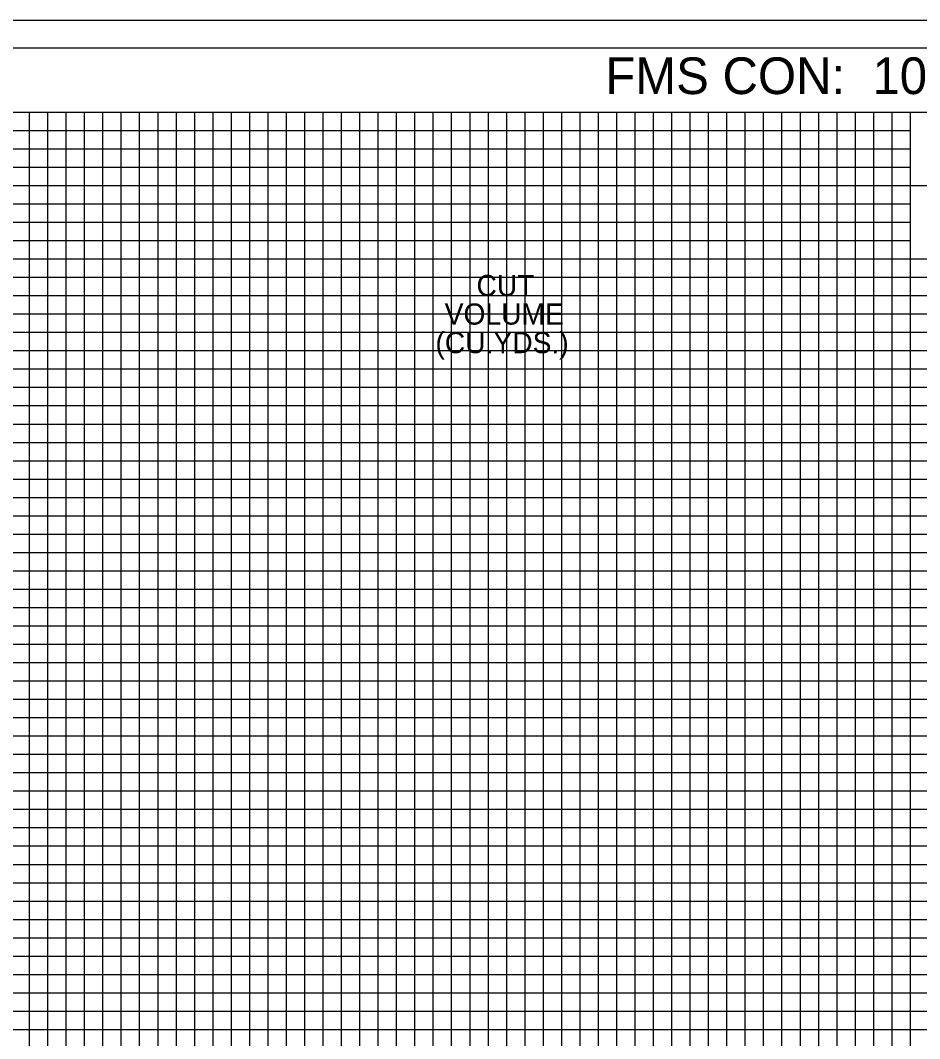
# Model space of a CAD drawing. Extents: x -10 to 342, y -5 to 215.
# Drawn here: x 258.5 to 307.5, y 159.5 to 215 of the extents above; entities that cross this region are included whole.
import ezdxf

# ---------------------------------------------------------------- set-up
doc = ezdxf.new("R2010")
doc.units = 0
for name, color, linetype in [('SHEET_BORDER', 7, 'Continuous'), ('SHEET_BORDER_TX', 7, 'Continuous'), ('SHEET_PLOTTING_SHAPE', 7, 'Continuous'), ('SHEET_PROJ_NUMBER', 7, 'Continuous'), ('XS_SHEET_EW_TX_VOLUME', 7, 'Continuous'), ('XS_SHEET_MAJOR_GRIDS', 7, 'Continuous'), ('XS_SHEET_MEDIUM_GRIDS', 7, 'Continuous'), ('XS_SHEET_MINOR_GRIDS', 7, 'Continuous')]:
    doc.layers.add(name, color=color, linetype=linetype)

msp = doc.modelspace()

# ---------------------------------------------------------------- linework, layer by layer
at = {"layer": 'SHEET_BORDER'}
for p, q in [((-9.8, 213.5), (342.2, 213.5)), ((5, 210), (340, 210)), ((307, 206), (340, 206))]:
    msp.add_line(p, q, dxfattribs=at)
at = {"layer": 'SHEET_PLOTTING_SHAPE'}
msp.add_lwpolyline([(-3.8, -5), (342.2, -5), (342.2, 215), (-3.8, 215)], close=True, dxfattribs=at)
at = {"layer": 'SHEET_PROJ_NUMBER'}
for q in [(307, 210), (340, 202)]:
    msp.add_line((307, 202), q, dxfattribs=at)
at = {"layer": 'XS_SHEET_MAJOR_GRIDS'}
for p, q in [((260, 0), (260, 210)), ((270, 0), (270, 210)), ((280, 0), (280, 210)), ((290, 0), (290, 210)), ((300, 0), (300, 210)), ((5, 200), (340, 200)), ((5, 190), (340, 190)), ((5, 180), (340, 180)), ((5, 170), (340, 170)), ((5, 160), (340, 160))]:
    msp.add_line(p, q, dxfattribs=at)
at = {"layer": 'XS_SHEET_MEDIUM_GRIDS'}
for p, q in [((265, 0), (265, 210)), ((275, 0), (275, 210)), ((285, 0), (285, 210)), ((295, 0), (295, 210)), ((305, 0), (305, 210)), ((5, 205), (307, 205)), ((5, 195), (340, 195)), ((5, 185), (340, 185)), ((5, 175), (340, 175)), ((5, 165), (340, 165))]:
    msp.add_line(p, q, dxfattribs=at)
at = {"layer": 'XS_SHEET_MINOR_GRIDS'}
for p, q in [((259, 0), (259, 210)), ((261, 0), (261, 210)), ((262, 0), (262, 210)), ((263, 0), (263, 210)), ((264, 0), (264, 210)), ((266, 0), (266, 210)), ((267, 0), (267, 210)), ((268, 0), (268, 210)), ((269, 0), (269, 210)), ((271, 0), (271, 210)), ((272, 0), (272, 210)), ((273, 0), (273, 210)), ((274, 0), (274, 210)), ((276, 0), (276, 210)), ((277, 0), (277, 210)), ((278, 0), (278, 210)), ((279, 0), (279, 210)), ((281, 0), (281, 210)), ((282, 0), (282, 210)), ((283, 0), (283, 210)), ((284, 0), (284, 210)), ((286, 0), (286, 210)), ((287, 0), (287, 210)), ((288, 0), (288, 210)), ((289, 0), (289, 210)), ((291, 0), (291, 210)), ((292, 0), (292, 210)), ((293, 0), (293, 210)), ((294, 0), (294, 210)), ((296, 0), (296, 210)), ((297, 0), (297, 210)), ((298, 0), (298, 210)), ((299, 0), (299, 210)), ((301, 0), (301, 210)), ((302, 0), (302, 210)), ((303, 0), (303, 210)), ((304, 0), (304, 210)), ((306, 0), (306, 210)), ((5, 209), (307, 209)), ((5, 208), (307, 208)), ((5, 207), (307, 207)), ((5, 206), (307, 206)), ((5, 204), (307, 204)), ((5, 203), (307, 203)), ((5, 202), (307, 202)), ((307, 0), (307, 202)), ((5, 201), (340, 201)), ((5, 199), (340, 199)), ((5, 198), (340, 198)), ((5, 197), (340, 197)), ((5, 196), (340, 196)), ((5, 194), (340, 194)), ((5, 193), (340, 193)), ((5, 192), (340, 192)), ((5, 191), (340, 191)), ((5, 189), (340, 189)), ((5, 188), (340, 188)), ((5, 187), (340, 187)), ((5, 186), (340, 186)), ((5, 184), (340, 184)), ((5, 183), (340, 183)), ((5, 182), (340, 182)), ((5, 181), (340, 181)), ((5, 179), (340, 179)), ((5, 178), (340, 178)), ((5, 177), (340, 177)), ((5, 176), (340, 176)), ((5, 174), (340, 174)), ((5, 173), (340, 173)), ((5, 172), (340, 172)), ((5, 171), (340, 171)), ((5, 169), (340, 169)), ((5, 168), (340, 168)), ((5, 167), (340, 167)), ((5, 166), (340, 166)), ((5, 164), (340, 164)), ((5, 163), (340, 163)), ((5, 162), (340, 162)), ((5, 161), (340, 161))]:
    msp.add_line(p, q, dxfattribs=at)

# ---------------------------------------------------------------- texts
at = {"layer": 'SHEET_BORDER_TX'}
msp.add_text('FMS CON:  106687 / 301000', height=2, dxfattribs=at).set_placement((290.37, 210.982))
at = {"layer": 'XS_SHEET_EW_TX_VOLUME'}
for s, p in [('CUT', (283.353, 199.975)), ('VOLUME', (281.619, 198.418)), ('(CU.YDS.)', (281.116, 196.86))]:
    msp.add_text(s, height=1.15, dxfattribs=at).set_placement(p)

doc.saveas('drawing.dxf')
